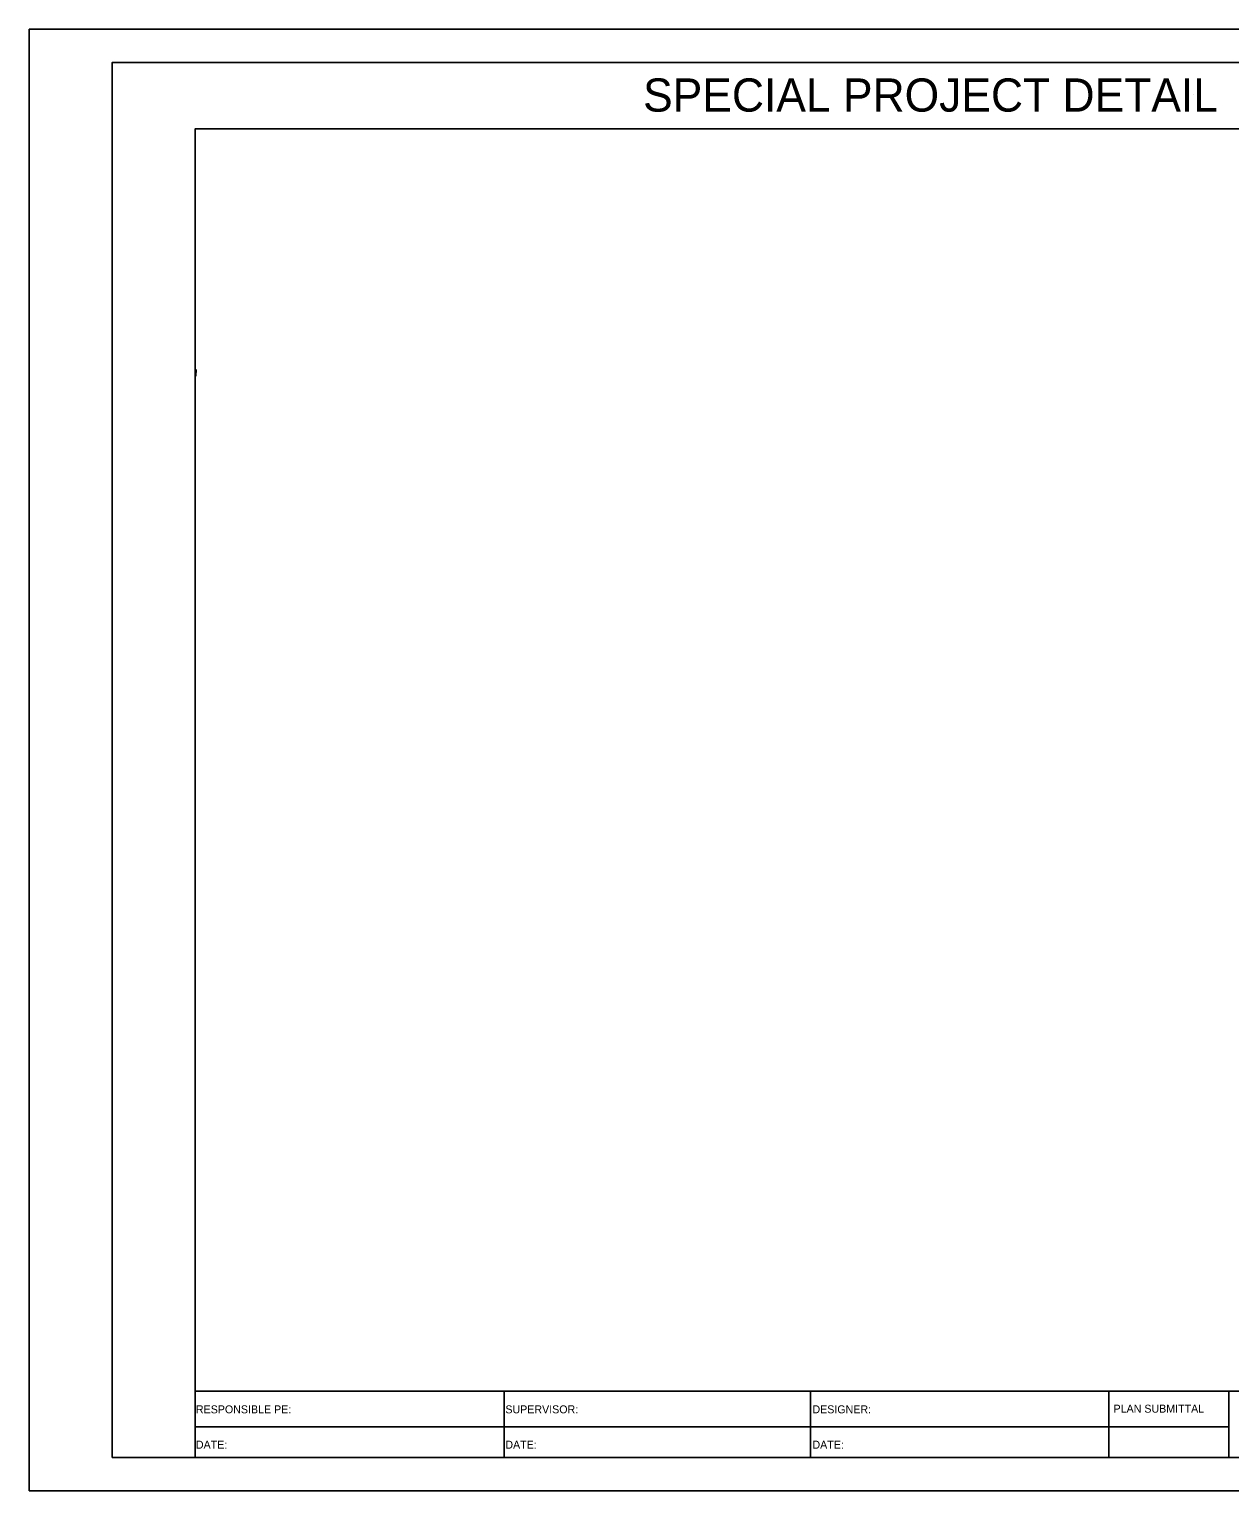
# Model space of a CAD drawing. Extents: x 515543 to 517243, y 661761 to 662861.
# Drawn here: x 515543 to 516446, y 661761 to 662861 of the extents above; entities that cross this region are included whole.
import ezdxf

# ---------------------------------------------------------------- set-up
doc = ezdxf.new("R2010")
doc.units = 0
for name, color, linetype in [('2', 7, 'Continuous'), ('ANNO-SHT', 7, 'Continuous'), ('ANNO-TXT', 7, 'Continuous'), ('AXIS', 7, 'Continuous'), ('DRAINAGE', 7, 'Continuous'), ('Level 1', 7, 'Continuous'), ('Level 62', 7, 'Continuous'), ('SHT-BDR', 7, 'Continuous'), ('SHT-BNDRY', 7, 'Continuous')]:
    doc.layers.add(name, color=color, linetype=linetype)

# ---------------------------------------------------------------- blocks, each defined once
blk = doc.blocks.new('SC47208')
at = {"layer": 'Level 1'}
blk.add_line((0, 0), (0, 0), dxfattribs=at)

msp = doc.modelspace()

# ---------------------------------------------------------------- linework, layer by layer
at = {"layer": '2'}
msp.add_lwpolyline([(515668.1, 662604.6), (515668, 662599.6)], dxfattribs=at)
msp.add_lwpolyline([(515668.1, 662604.6), (515668, 662599.6)], dxfattribs=at)
at = {"layer": 'AXIS'}
msp.add_line((515667.5, 662385.7), (515667.5, 662385.8), dxfattribs=at)
at = {"layer": 'Level 62'}
msp.add_lwpolyline([(515542.5, 661760.7), (517242.5, 661760.7), (517242.5, 662860.7), (515542.5, 662860.7)], close=True, dxfattribs=at)
at = {"layer": 'SHT-BDR'}
msp.add_lwpolyline([(515667.5, 661835.8), (517167.5, 661835.8), (517167.5, 662785.8), (515667.5, 662785.8)], close=True, dxfattribs=at)
at = {"layer": 'SHT-BNDRY'}
for p, q in [((515667.5, 661785.7), (515667.5, 661835.8)), ((515900.1, 661835.8), (515900.1, 661785.7)), ((516130.8, 661785.7), (516130.8, 661835.8)), ((516355.4, 661785.7), (516355.4, 661835.8)), ((516445.6, 661785.7), (516445.6, 661835.8)), ((515667.5, 661808.8), (516445.6, 661808.8))]:
    msp.add_line(p, q, dxfattribs=at)
msp.add_lwpolyline([(515605, 661785.7), (517217.5, 661785.7), (517217.5, 662835.7), (515605, 662835.7)], close=True, dxfattribs=at)

# ---------------------------------------------------------------- block references
at = {"layer": 'DRAINAGE', "xscale": 1.0000020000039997, "yscale": 1.0000020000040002, "rotation": -116.41666666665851}
msp.add_blockref('SC47208', (516419.1, 662811.7), dxfattribs=at)
msp.add_blockref('SC47208', (516419.1, 662811.7), dxfattribs=at)

# ---------------------------------------------------------------- texts
at = {"layer": 'ANNO-SHT'}
msp.add_text('         SPECIAL PROJECT DETAIL         ', height=24.998, dxfattribs=at).set_placement((515921.1, 662798.7))
at = {"layer": 'ANNO-TXT'}
for s, p in [('RESPONSIBLE PE:', (515668, 661819)), ('SUPERVISOR:', (515901, 661819)), ('DESIGNER:', (516132.2, 661819)), ('PLAN SUBMITTAL', (516358.9, 661819.5)), ('DATE:', (515668, 661792.4)), ('DATE:', (515901, 661792.4)), ('DATE:', (516132.2, 661792.4))]:
    msp.add_text(s, height=6, rotation=360, dxfattribs=at).set_placement(p)

doc.saveas('drawing.dxf')
